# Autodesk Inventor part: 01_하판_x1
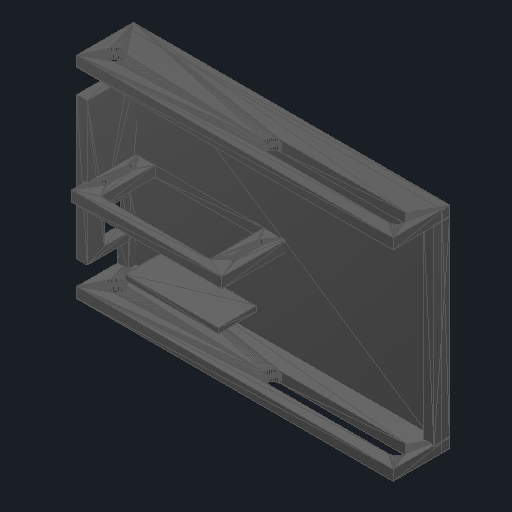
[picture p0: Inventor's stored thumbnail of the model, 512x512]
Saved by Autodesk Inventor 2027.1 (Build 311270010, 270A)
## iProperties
Created: 2026-11
Part Number: 01_하판_x1
Material: 일반
Document SubType Name: Modeling
Designer: djshs
Density: 1 g/cm^3
Appearance: 기본값
Author: djshs
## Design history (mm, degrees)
node "01_하판_x1"
  node "MeshFeature1"
